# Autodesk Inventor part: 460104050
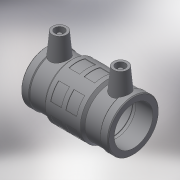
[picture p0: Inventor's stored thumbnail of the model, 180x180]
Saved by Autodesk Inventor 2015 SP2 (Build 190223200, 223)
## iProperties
Created: 2017-06
Part Number: 460104050
Material: Generic
Description: PLASSON LIGHTFIT COUPLER 50
Document SubType Name: Modeling
Designer: KIM
Mass: 89.5427 g
Surface Area: 304.58 cm^2
Volume: 89.5427 cm^3
Density: 1 g/cm^3
Appearance: Default
Author: KIM
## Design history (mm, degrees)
derived "460104.ipt"
feature "Solid1::460104.ipt"
tag "TaggingFeature1"
body "Solid1"
other parameters: "d14" = 17.6296, "d15" = 49, "d16" = 49, "d17" = 49.5, "d19" = 3.52592, "d20" = 168 deg, "d22" = 63.92, "d23" = 68, "d24" = 62.0024, "d25" = 135 deg, "d27" = 135 deg, "d29" = 52, "d35" = 15, "d39" = 5 deg, "d44" = 4, "d46" = 14, "d47" = 0, "d52" = 66.64, "d53" = 5, "d54" = 5, "d55" = 5, "d56" = 35 deg, "d58" = 360 deg, "d60" = 9.8, "d61" = 135 deg, "d62" = 38, "d63" = 3, "d64" = 0, "L_1" = 49, "D_" = 68, "A_" = 52, "d_2" = 8
